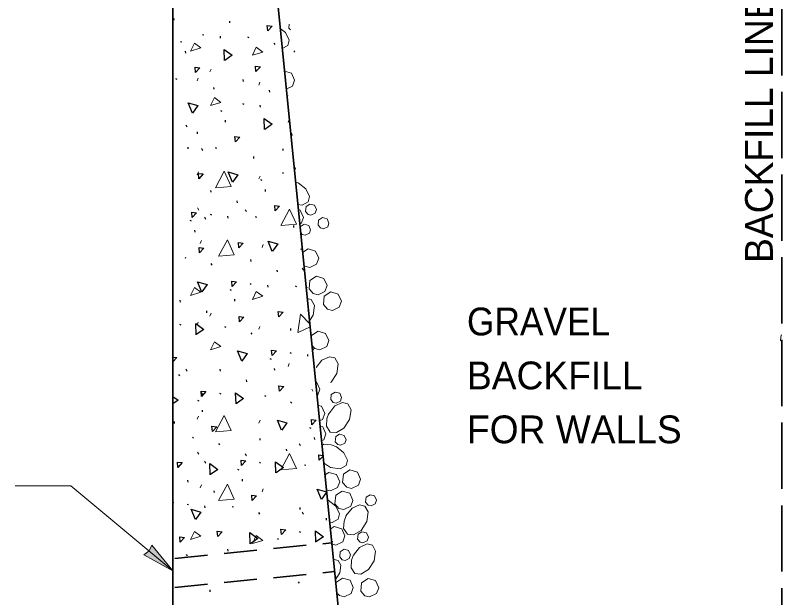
# Model space of a CAD drawing. Extents: x 17672 to 18472, y -9785 to -9267.
# Drawn here: x 17771.1 to 17868.5, y -9416.4 to -9342.5 of the extents above; entities that cross this region are included whole.
import ezdxf

# ---------------------------------------------------------------- set-up
doc = ezdxf.new("R2010")
doc.units = 0
doc.header["$LTSCALE"] = 1.4
doc.linetypes.add('LONG_DASHED', pattern=[7.5, 6, -1.5])
doc.linetypes.add('MEDIUM_DASHED', pattern=[4.5, 3, -1.5])
for name, color, linetype, lineweight in [('1', 7, 'Continuous', 13), ('15', 7, 'Continuous', 13), ('16', 7, 'Continuous', 13), ('20', 7, 'Continuous', 25)]:
    doc.layers.add(name, color=color, linetype=linetype, lineweight=lineweight)

msp = doc.modelspace()

# ---------------------------------------------------------------- hatches: boundary and pattern name
at = {"layer": '16'}
msp.add_hatch(color=256, dxfattribs=at).paths.add_polyline_path([(17791.158, -9413.001), (17788.481, -9409.751), (17788.123, -9410.472), (17787.454, -9410.982)])

# ---------------------------------------------------------------- linework, layer by layer
at = {"layer": '1', "linetype": 'LONG_DASHED', "lineweight": 35}
msp.add_line((17868.469, -9455.105), (17868.469, -9325.672), dxfattribs=at)
at = {"layer": '1', "lineweight": 25}
for p, q in [((17791.315, -9343.094), (17791.29, -9342.854)), ((17798.39, -9343.448), (17798.365, -9343.209)), ((17794.924, -9344.896), (17795.082, -9344.975)), ((17797.209, -9345.371), (17797.184, -9345.131)), ((17800.644, -9345.197), (17800.802, -9345.276)), ((17792.138, -9345.785), (17792.296, -9345.864)), ((17803.962, -9345.994), (17804.094, -9346.173)), ((17792.784, -9347.276), (17792.759, -9347.036)), ((17791.474, -9350.492), (17791.632, -9350.57)), ((17800.107, -9350.879), (17800.082, -9350.639)), ((17796.382, -9351.871), (17796.357, -9351.631)), ((17803.457, -9352.225), (17803.432, -9351.985)), ((17799.991, -9353.673), (17800.149, -9353.751)), ((17802.277, -9354.147), (17802.251, -9353.907)), ((17805.711, -9353.974), (17805.775, -9354.005)), ((17797.205, -9354.562), (17797.363, -9354.64)), ((17797.851, -9356.052), (17797.826, -9355.812)), ((17794.287, -9357.519), (17794.262, -9357.279)), ((17793.107, -9359.441), (17793.082, -9359.202)), ((17796.541, -9359.268), (17796.699, -9359.346)), ((17805.174, -9359.656), (17805.149, -9359.416)), ((17801.449, -9360.647), (17801.424, -9360.407)), ((17805.058, -9362.449), (17805.216, -9362.528)), ((17802.272, -9363.338), (17802.43, -9363.416)), ((17796.005, -9364.95), (17795.979, -9364.71)), ((17802.918, -9364.829), (17802.893, -9364.588)), ((17799.354, -9366.295), (17799.329, -9366.056)), ((17795.888, -9367.743), (17796.046, -9367.822)), ((17793.321, -9368.506), (17793.479, -9368.584)), ((17798.174, -9368.218), (17798.149, -9367.978)), ((17801.608, -9368.044), (17801.766, -9368.123)), ((17793.967, -9369.997), (17793.941, -9369.757)), ((17806.516, -9369.424), (17806.491, -9369.184)), ((17807.339, -9372.115), (17807.497, -9372.193)), ((17792.657, -9373.212), (17792.815, -9373.291)), ((17801.072, -9373.726), (17801.046, -9373.486)), ((17795.975, -9374.009), (17796.107, -9374.188)), ((17804.421, -9375.072), (17804.396, -9374.832)), ((17800.955, -9376.52), (17801.113, -9376.598)), ((17798.388, -9377.283), (17798.546, -9377.361)), ((17803.241, -9376.994), (17803.216, -9376.754)), ((17806.675, -9376.821), (17806.834, -9376.899)), ((17799.034, -9378.773), (17799.008, -9378.533)), ((17792.12, -9378.894), (17792.095, -9378.654)), ((17795.47, -9380.24), (17795.445, -9380)), ((17792.004, -9381.688), (17792.162, -9381.766)), ((17797.724, -9381.989), (17797.882, -9382.067)), ((17806.139, -9382.503), (17806.113, -9382.263)), ((17801.042, -9382.786), (17801.174, -9382.964)), ((17806.022, -9385.296), (17806.18, -9385.374)), ((17803.455, -9386.059), (17803.613, -9386.137)), ((17808.308, -9385.77), (17808.283, -9385.531)), ((17804.101, -9387.55), (17804.075, -9387.309)), ((17791.872, -9388.08), (17792.004, -9388.258)), ((17797.187, -9387.671), (17797.162, -9387.431)), ((17800.537, -9389.016), (17800.512, -9388.777)), ((17797.071, -9390.464), (17797.229, -9390.543)), ((17802.791, -9390.765), (17802.949, -9390.844)), ((17794.285, -9391.353), (17794.443, -9391.431)), ((17806.109, -9391.562), (17806.241, -9391.74)), ((17794.931, -9392.844), (17794.906, -9392.604)), ((17791.367, -9394.311), (17791.342, -9394.071)), ((17808.522, -9394.835), (17808.68, -9394.914)), ((17793.621, -9396.059), (17793.779, -9396.138)), ((17809.168, -9396.326), (17809.142, -9396.086)), ((17796.939, -9396.856), (17797.071, -9397.035)), ((17802.254, -9396.447), (17802.229, -9396.207)), ((17805.604, -9397.793), (17805.579, -9397.553)), ((17810.22, -9398.455), (17809.744, -9398.972)), ((17802.138, -9399.241), (17802.296, -9399.319)), ((17807.858, -9399.542), (17808.016, -9399.62)), ((17799.352, -9400.13), (17799.51, -9400.208)), ((17793.085, -9401.741), (17793.059, -9401.501)), ((17799.998, -9401.62), (17799.973, -9401.38)), ((17796.434, -9403.087), (17796.409, -9402.847)), ((17810.678, -9403.034), (17810.044, -9403.935)), ((17792.968, -9404.535), (17793.126, -9404.613)), ((17795.254, -9405.009), (17795.229, -9404.769)), ((17798.688, -9404.836), (17798.847, -9404.914)), ((17802.006, -9405.633), (17802.138, -9405.811)), ((17807.321, -9405.224), (17807.296, -9404.984)), ((17810.671, -9406.569), (17810.646, -9406.329)), ((17807.205, -9408.017), (17807.363, -9408.095)), ((17804.419, -9408.906), (17804.577, -9408.984)), ((17798.152, -9410.518), (17798.126, -9410.278)), ((17792.837, -9410.927), (17792.968, -9411.105)), ((17807.073, -9414.409), (17807.205, -9414.587)), ((17795.895, -9415.691), (17795.87, -9415.451))]:
    msp.add_line(p, q, dxfattribs=at)
at = {"layer": '1'}
for p, q in [((17805.892, -9344.102), (17805.936, -9343.606)), ((17806.083, -9344.321), (17805.892, -9344.102)), ((17806.521, -9347.14), (17806.632, -9347)), ((17795.861, -9349.667), (17796.033, -9349.295)), ((17794.216, -9350.802), (17794.371, -9350.444)), ((17802.06, -9351.332), (17802.214, -9350.974)), ((17805.66, -9352.874), (17805.745, -9352.658)), ((17805.773, -9356.067), (17805.927, -9355.694)), ((17792.802, -9356.41), (17792.974, -9356.658)), ((17794.775, -9359.393), (17794.944, -9359.641)), ((17794.231, -9362.748), (17794.386, -9362.373)), ((17802.074, -9363.261), (17802.231, -9362.903)), ((17806.736, -9363.632), (17807.109, -9363.778)), ((17794.278, -9366.942), (17794.449, -9367.204)), ((17800.337, -9367.158), (17800.506, -9367.408)), ((17795.162, -9368.106), (17795.334, -9368.354)), ((17794.618, -9371.462), (17794.775, -9371.089)), ((17802.479, -9371.974), (17802.636, -9371.601)), ((17807.557, -9374.584), (17807.729, -9374.832)), ((17808.07, -9376.957), (17808.238, -9377.023)), ((17795.861, -9380.673), (17796.033, -9380.3)), ((17794.216, -9381.807), (17794.371, -9381.45)), ((17802.06, -9382.334), (17802.214, -9381.977)), ((17808.579, -9382.043), (17807.062, -9382.753)), ((17868.469, -9383.896), (17868.332, -9383.738)), ((17808.941, -9385.103), (17809.064, -9384.789)), ((17805.773, -9387.072), (17805.927, -9386.7)), ((17792.802, -9387.415), (17792.974, -9387.663)), ((17808.785, -9389.947), (17808.942, -9390.209)), ((17794.775, -9390.396), (17794.944, -9390.646)), ((17794.231, -9393.751), (17794.386, -9393.379)), ((17802.074, -9394.263), (17802.231, -9393.908)), ((17807.17, -9396.874), (17807.341, -9397.121)), ((17794.278, -9397.945), (17794.449, -9398.209)), ((17800.337, -9398.163), (17800.506, -9398.41)), ((17795.162, -9399.111), (17795.334, -9399.359)), ((17794.618, -9402.467), (17794.775, -9402.092)), ((17802.479, -9402.979), (17802.636, -9402.607)), ((17810.882, -9404.068), (17810.923, -9404.084)), ((17807.557, -9405.587), (17807.729, -9405.837)), ((17811.299, -9409.242), (17811.463, -9409.307))]:
    msp.add_line(p, q, dxfattribs=at)
at = {"layer": '1', "linetype": 'MEDIUM_DASHED', "lineweight": 35}
for p, q in [((17791.381, -9411.45), (17811.322, -9409.46)), ((17791.378, -9415.143), (17811.687, -9413.116))]:
    msp.add_line(p, q, dxfattribs=at)
at = {"layer": '1', "lineweight": 35}
msp.add_lwpolyline([(17791.158, -9452.247), (17791.158, -9320.182), (17802.354, -9319.797), (17815.601, -9452.266), (17791.158, -9452.266)], close=True, dxfattribs=at)
at = {"layer": '1', "lineweight": 25}
for points in [[(17803.189, -9344.463), (17803.137, -9343.786), (17803.745, -9343.859)], [(17794.019, -9349.757), (17793.967, -9349.08), (17794.575, -9349.154)], [(17801.704, -9349.611), (17801.653, -9348.934), (17802.26, -9349.007)], [(17799.086, -9358.534), (17799.034, -9357.857), (17799.642, -9357.93)], [(17794.452, -9363.23), (17794.4, -9362.554), (17795.008, -9362.627)], [(17804.153, -9367.31), (17804.101, -9366.633), (17804.709, -9366.706)], [(17793.607, -9368.143), (17793.556, -9367.466), (17794.163, -9367.54)], [(17799.519, -9372.007), (17799.467, -9371.33), (17800.075, -9371.403)], [(17794.543, -9372.643), (17794.491, -9371.966), (17795.099, -9372.039)], [(17798.674, -9376.92), (17798.623, -9376.243), (17799.23, -9376.316)], [(17804.586, -9380.783), (17804.534, -9380.106), (17805.142, -9380.18)], [(17799.61, -9381.419), (17799.558, -9380.742), (17800.166, -9380.816)], [(17803.741, -9385.696), (17803.69, -9385.019), (17804.298, -9385.092)], [(17794.79, -9390.864), (17794.738, -9390.187), (17795.346, -9390.261)], [(17804.677, -9390.196), (17804.625, -9389.519), (17805.233, -9389.592)], [(17808.808, -9394.473), (17808.757, -9393.796), (17809.365, -9393.869)], [(17796.166, -9395.325), (17796.114, -9394.648), (17796.722, -9394.722)], [(17799.857, -9399.641), (17799.805, -9398.964), (17800.413, -9399.037)], [(17791.774, -9399.882), (17791.722, -9399.205), (17792.33, -9399.278)], [(17801.233, -9404.102), (17801.181, -9403.425), (17801.789, -9403.498)], [(17804.924, -9408.417), (17804.873, -9407.74), (17805.48, -9407.813)], [(17792.063, -9409.396), (17792.012, -9408.719), (17792.619, -9408.792)], [(17796.841, -9408.658), (17796.789, -9407.981), (17797.397, -9408.055)]]:
    msp.add_lwpolyline(points, close=True, dxfattribs=at)
at = {"layer": '1'}
for points in [[(17804.786, -9344.132), (17805.468, -9344.671), (17805.92, -9345.637), (17805.757, -9346.315), (17805.044, -9346.708)], [(17805.329, -9349.564), (17806.195, -9349.813), (17806.607, -9350.726), (17806.333, -9351.469), (17805.557, -9351.845)], [(17806.091, -9357.184), (17806.302, -9357.65), (17806.173, -9358)], [(17806.522, -9361.486), (17806.719, -9361.924), (17806.598, -9362.252)], [(17796.562, -9364.364), (17797.665, -9362.28), (17798.533, -9364.207), (17796.609, -9364.364)], [(17807.06, -9363.753), (17808.034, -9364.525), (17808.486, -9365.49), (17808.323, -9366.167), (17807.569, -9366.584), (17807.024, -9366.507)], [(17808.007, -9367.406), (17808.064, -9366.765), (17808.56, -9366.439), (17809.129, -9366.603), (17809.376, -9367.151), (17809.212, -9367.596), (17808.685, -9367.852), (17808.313, -9367.759), (17808.007, -9367.407)], [(17804.871, -9369.177), (17805.974, -9367.096), (17806.829, -9369.008), (17804.917, -9369.177)], [(17807.091, -9367.175), (17807.307, -9367.238), (17807.72, -9368.15), (17807.445, -9368.894), (17807.271, -9368.979)], [(17809.602, -9369.128), (17809.66, -9368.486), (17810.156, -9368.161), (17810.726, -9368.325), (17810.973, -9368.872), (17810.809, -9369.318), (17810.281, -9369.574), (17809.91, -9369.481), (17809.603, -9369.128)], [(17807.321, -9369.481), (17807.335, -9369.327), (17807.831, -9369.001), (17808.4, -9369.165), (17808.648, -9369.713), (17808.483, -9370.159), (17807.955, -9370.414), (17807.584, -9370.321), (17807.382, -9370.089)], [(17796.964, -9373.077), (17798.067, -9370.996), (17798.922, -9372.905), (17796.996, -9373.077)], [(17807.632, -9372.591), (17808.32, -9372.14), (17809.27, -9372.413), (17809.682, -9373.325), (17809.407, -9374.069), (17808.528, -9374.495), (17807.909, -9374.339), (17807.794, -9374.206)], [(17807.868, -9374.948), (17807.929, -9375.082), (17807.891, -9375.183)], [(17808.455, -9377.23), (17808.55, -9376.16), (17809.377, -9375.617), (17810.326, -9375.891), (17810.738, -9376.803), (17810.464, -9377.547), (17809.585, -9377.973), (17808.966, -9377.817), (17808.455, -9377.229)], [(17808.218, -9378.444), (17808.727, -9378.567), (17809.144, -9379.321), (17808.97, -9380.552), (17808.5, -9381.264)], [(17807.03, -9382.753), (17807.341, -9380.425), (17808.54, -9381.648)], [(17808.731, -9383.578), (17808.77, -9383.145), (17809.596, -9382.603), (17810.546, -9382.876), (17810.958, -9383.789), (17810.683, -9384.532), (17809.805, -9384.959), (17809.186, -9384.803), (17808.81, -9384.371)], [(17868.331, -9383.738), (17868.389, -9383.096), (17868.469, -9383.043)], [(17809.348, -9387.197), (17810.076, -9386.279), (17811.041, -9385.827), (17811.718, -9385.991), (17812.135, -9386.745), (17811.961, -9387.976), (17811.232, -9389.08), (17811.184, -9389.109)], [(17809.341, -9389.011), (17809.403, -9389.029), (17809.815, -9389.942), (17809.541, -9390.685), (17809.514, -9390.698)], [(17811.216, -9391.279), (17811.274, -9390.637), (17811.77, -9390.312), (17812.34, -9390.475), (17812.586, -9391.023), (17812.422, -9391.469), (17811.894, -9391.725), (17811.523, -9391.631), (17811.217, -9391.279)], [(17809.649, -9392.02), (17810.022, -9392.127), (17810.434, -9393.04), (17810.16, -9393.784), (17809.845, -9393.936)], [(17810.942, -9393.064), (17811.714, -9392.089), (17812.679, -9391.638), (17813.356, -9391.801), (17813.773, -9392.555), (17813.599, -9393.786), (17812.87, -9394.89), (17811.914, -9395.465), (17811.147, -9395.393), (17810.651, -9394.653), (17810.695, -9393.71), (17810.968, -9393.015)], [(17796.562, -9395.366), (17797.665, -9393.285), (17798.533, -9395.212), (17796.609, -9395.366)], [(17809.879, -9395.049), (17809.932, -9395.166), (17809.9, -9395.253)], [(17809.918, -9394.648), (17810.177, -9394.723), (17810.59, -9395.635), (17810.316, -9396.379), (17810.106, -9396.48)], [(17811.778, -9396.621), (17811.836, -9395.979), (17812.331, -9395.654), (17812.902, -9395.817), (17813.148, -9396.365), (17812.984, -9396.811), (17812.456, -9397.067), (17812.085, -9396.973), (17811.779, -9396.621)], [(17810.165, -9397.058), (17810.316, -9396.956), (17811.259, -9397), (17811.954, -9397.273)], [(17811.905, -9397.247), (17812.88, -9398.019), (17813.331, -9398.985), (17813.168, -9399.662), (17812.414, -9400.078), (17811.183, -9399.905), (17810.404, -9399.39)], [(17804.871, -9400.183), (17805.974, -9398.102), (17806.829, -9400.011), (17804.917, -9400.183)], [(17810.548, -9400.8), (17810.973, -9400.521), (17811.923, -9400.794), (17812.335, -9401.706), (17812.061, -9402.45), (17811.181, -9402.876), (17810.749, -9402.767)], [(17796.964, -9404.082), (17798.067, -9401.999), (17798.922, -9403.911), (17796.996, -9404.082)], [(17811.735, -9404.5), (17811.831, -9403.43), (17812.657, -9402.888), (17813.606, -9403.161), (17814.019, -9404.073), (17813.744, -9404.817), (17812.865, -9405.243), (17812.246, -9405.088), (17811.736, -9404.5)], [(17815.634, -9404.32), (17815.692, -9403.678), (17816.187, -9403.352), (17816.757, -9403.516), (17817.004, -9404.063), (17816.84, -9404.51), (17816.312, -9404.765), (17815.941, -9404.672), (17815.634, -9404.319)], [(17810.882, -9404.065), (17811.848, -9404.83), (17812.3, -9405.796), (17812.137, -9406.473), (17811.382, -9406.89), (17811.168, -9406.859)], [(17813.131, -9406.054), (17813.903, -9405.079), (17814.869, -9404.628), (17815.545, -9404.791), (17815.962, -9405.545), (17815.788, -9406.776), (17815.059, -9407.881), (17814.103, -9408.455), (17813.336, -9408.383), (17812.84, -9407.643), (17812.884, -9406.7), (17813.157, -9406.005)], [(17811.25, -9407.656), (17811.645, -9407.397), (17812.594, -9407.67), (17813.006, -9408.582), (17812.732, -9409.326), (17811.853, -9409.753), (17811.454, -9409.652)], [(17814.069, -9411.04), (17814.841, -9410.065), (17815.806, -9409.613), (17816.483, -9409.776), (17816.9, -9410.531), (17816.726, -9411.762), (17815.997, -9412.866), (17815.041, -9413.441), (17814.274, -9413.368), (17813.778, -9412.629), (17813.822, -9411.685), (17814.095, -9410.99)], [(17811.65, -9411.565), (17812.16, -9411.688), (17812.499, -9412.299), (17812.358, -9413.296), (17811.898, -9413.992)], [(17811.721, -9413.468), (17811.844, -9413.74), (17811.769, -9413.944)], [(17811.945, -9414.449), (17812.702, -9413.952), (17813.651, -9414.225), (17814.063, -9415.138), (17813.789, -9415.882), (17812.911, -9416.307), (17812.292, -9416.151), (17812.096, -9415.927)]]:
    msp.add_lwpolyline(points, dxfattribs=at)
for points in [[(17793.408, -9347.042), (17793.888, -9346.018), (17794.711, -9346.623)], [(17801.251, -9347.555), (17801.734, -9346.53), (17802.557, -9347.153)], [(17795.939, -9353.94), (17796.437, -9352.915), (17797.243, -9353.535)], [(17793.408, -9378.048), (17793.888, -9377.023), (17794.711, -9377.628)], [(17801.251, -9378.56), (17801.734, -9377.535), (17802.557, -9378.155)], [(17810.274, -9379.218), (17810.369, -9378.148), (17811.196, -9377.606), (17812.145, -9377.879), (17812.557, -9378.791), (17812.283, -9379.535), (17811.405, -9379.961), (17810.785, -9379.805)], [(17795.939, -9384.945), (17796.437, -9383.92), (17797.243, -9384.54)], [(17812.711, -9401.814), (17812.806, -9400.744), (17813.632, -9400.202), (17814.582, -9400.475), (17814.994, -9401.387), (17814.72, -9402.131), (17813.841, -9402.557), (17813.222, -9402.401)], [(17793.408, -9409.053), (17793.888, -9408.026), (17794.711, -9408.634)], [(17801.251, -9409.565), (17801.734, -9408.54), (17802.557, -9409.161)], [(17814.614, -9409.02), (17814.671, -9408.378), (17815.167, -9408.052), (17815.737, -9408.216), (17815.984, -9408.764), (17815.82, -9409.21), (17815.292, -9409.466), (17814.921, -9409.372)], [(17812.344, -9411.254), (17812.401, -9410.612), (17812.897, -9410.287), (17813.466, -9410.451), (17813.714, -9410.998), (17813.549, -9411.444), (17813.022, -9411.7), (17812.65, -9411.606)], [(17815.01, -9415.598), (17815.106, -9414.527), (17815.932, -9413.986), (17816.882, -9414.259), (17817.294, -9415.171), (17817.019, -9415.915), (17816.14, -9416.341), (17815.521, -9416.185)]]:
    msp.add_lwpolyline(points, close=True, dxfattribs=at)
at = {"layer": '1', "lineweight": 25}
for points in [[(17797.724, -9348.209), (17797.672, -9346.797), (17798.693, -9347.537), (17797.745, -9348.197)], [(17793.644, -9354.903), (17793.112, -9353.594), (17794.325, -9353.94), (17793.66, -9354.885)], [(17802.791, -9356.985), (17802.739, -9355.573), (17803.76, -9356.313), (17802.812, -9356.973)], [(17798.711, -9363.68), (17798.179, -9362.371), (17799.392, -9362.717), (17798.727, -9363.661)], [(17803.778, -9372.456), (17803.247, -9371.147), (17804.459, -9371.493), (17803.794, -9372.437)], [(17794.827, -9377.624), (17794.295, -9376.315), (17795.507, -9376.661), (17794.842, -9377.606)], [(17808.384, -9380.097), (17808.314, -9379.924), (17808.368, -9379.939)], [(17794.1, -9383.035), (17794.049, -9381.623), (17795.069, -9382.363), (17794.121, -9383.023)], [(17799.894, -9386.401), (17799.362, -9385.092), (17800.574, -9385.437), (17799.909, -9386.382)], [(17791.158, -9385.885), (17791.655, -9385.945), (17791.158, -9386.485)], [(17791.158, -9390.889), (17791.808, -9391.361), (17791.158, -9391.813)], [(17799.167, -9391.811), (17799.116, -9390.399), (17800.136, -9391.139), (17799.189, -9391.799)], [(17804.961, -9395.177), (17804.429, -9393.868), (17805.641, -9394.214), (17804.977, -9395.158)], [(17809.744, -9398.972), (17809.692, -9398.295), (17810.21, -9398.358)], [(17795.906, -9400.809), (17795.854, -9399.397), (17796.875, -9400.137), (17795.927, -9400.797)], [(17804.234, -9400.588), (17804.183, -9399.176), (17805.203, -9399.915), (17804.256, -9400.575)], [(17810.028, -9403.953), (17809.496, -9402.644), (17810.672, -9402.98)], [(17791.158, -9404.321), (17791.243, -9404.331), (17791.158, -9404.424)], [(17794.006, -9406.52), (17793.474, -9405.211), (17794.686, -9405.557), (17794.021, -9406.501)], [(17800.973, -9409.586), (17800.921, -9408.174), (17801.942, -9408.913), (17800.994, -9409.573)], [(17809.301, -9409.364), (17809.25, -9407.952), (17810.27, -9408.692), (17809.323, -9409.352)]]:
    msp.add_lwpolyline(points, dxfattribs=at)
at = {"layer": '15'}
for p, q in [((17778.209, -9402.207), (17771.14, -9402.207)), ((17791.158, -9413.001), (17778.209, -9402.207))]:
    msp.add_line(p, q, dxfattribs=at)
at = {"layer": '16'}
msp.add_lwpolyline([(17791.158, -9413.001), (17788.481, -9409.751), (17788.123, -9410.472), (17787.454, -9410.982)], close=True, dxfattribs=at)

# ---------------------------------------------------------------- texts
at = {"layer": '20'}
msp.add_text('BACKFILL LINE', height=3.529, rotation=90, dxfattribs=at).set_placement((17867.349, -9373.92))
at = {"layer": '20', "width": 0.95}
msp.add_text('GRAVEL', height=3.529, dxfattribs=at).set_placement((17828.501, -9383.121))
at = {"layer": '20'}
for s, p in [('BACKFILL', (17828.501, -9389.972)), ('FOR WALLS', (17828.501, -9396.822))]:
    msp.add_text(s, height=3.529, dxfattribs=at).set_placement(p)

doc.saveas('drawing.dxf')
